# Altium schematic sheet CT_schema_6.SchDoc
size 368 x 336 mm
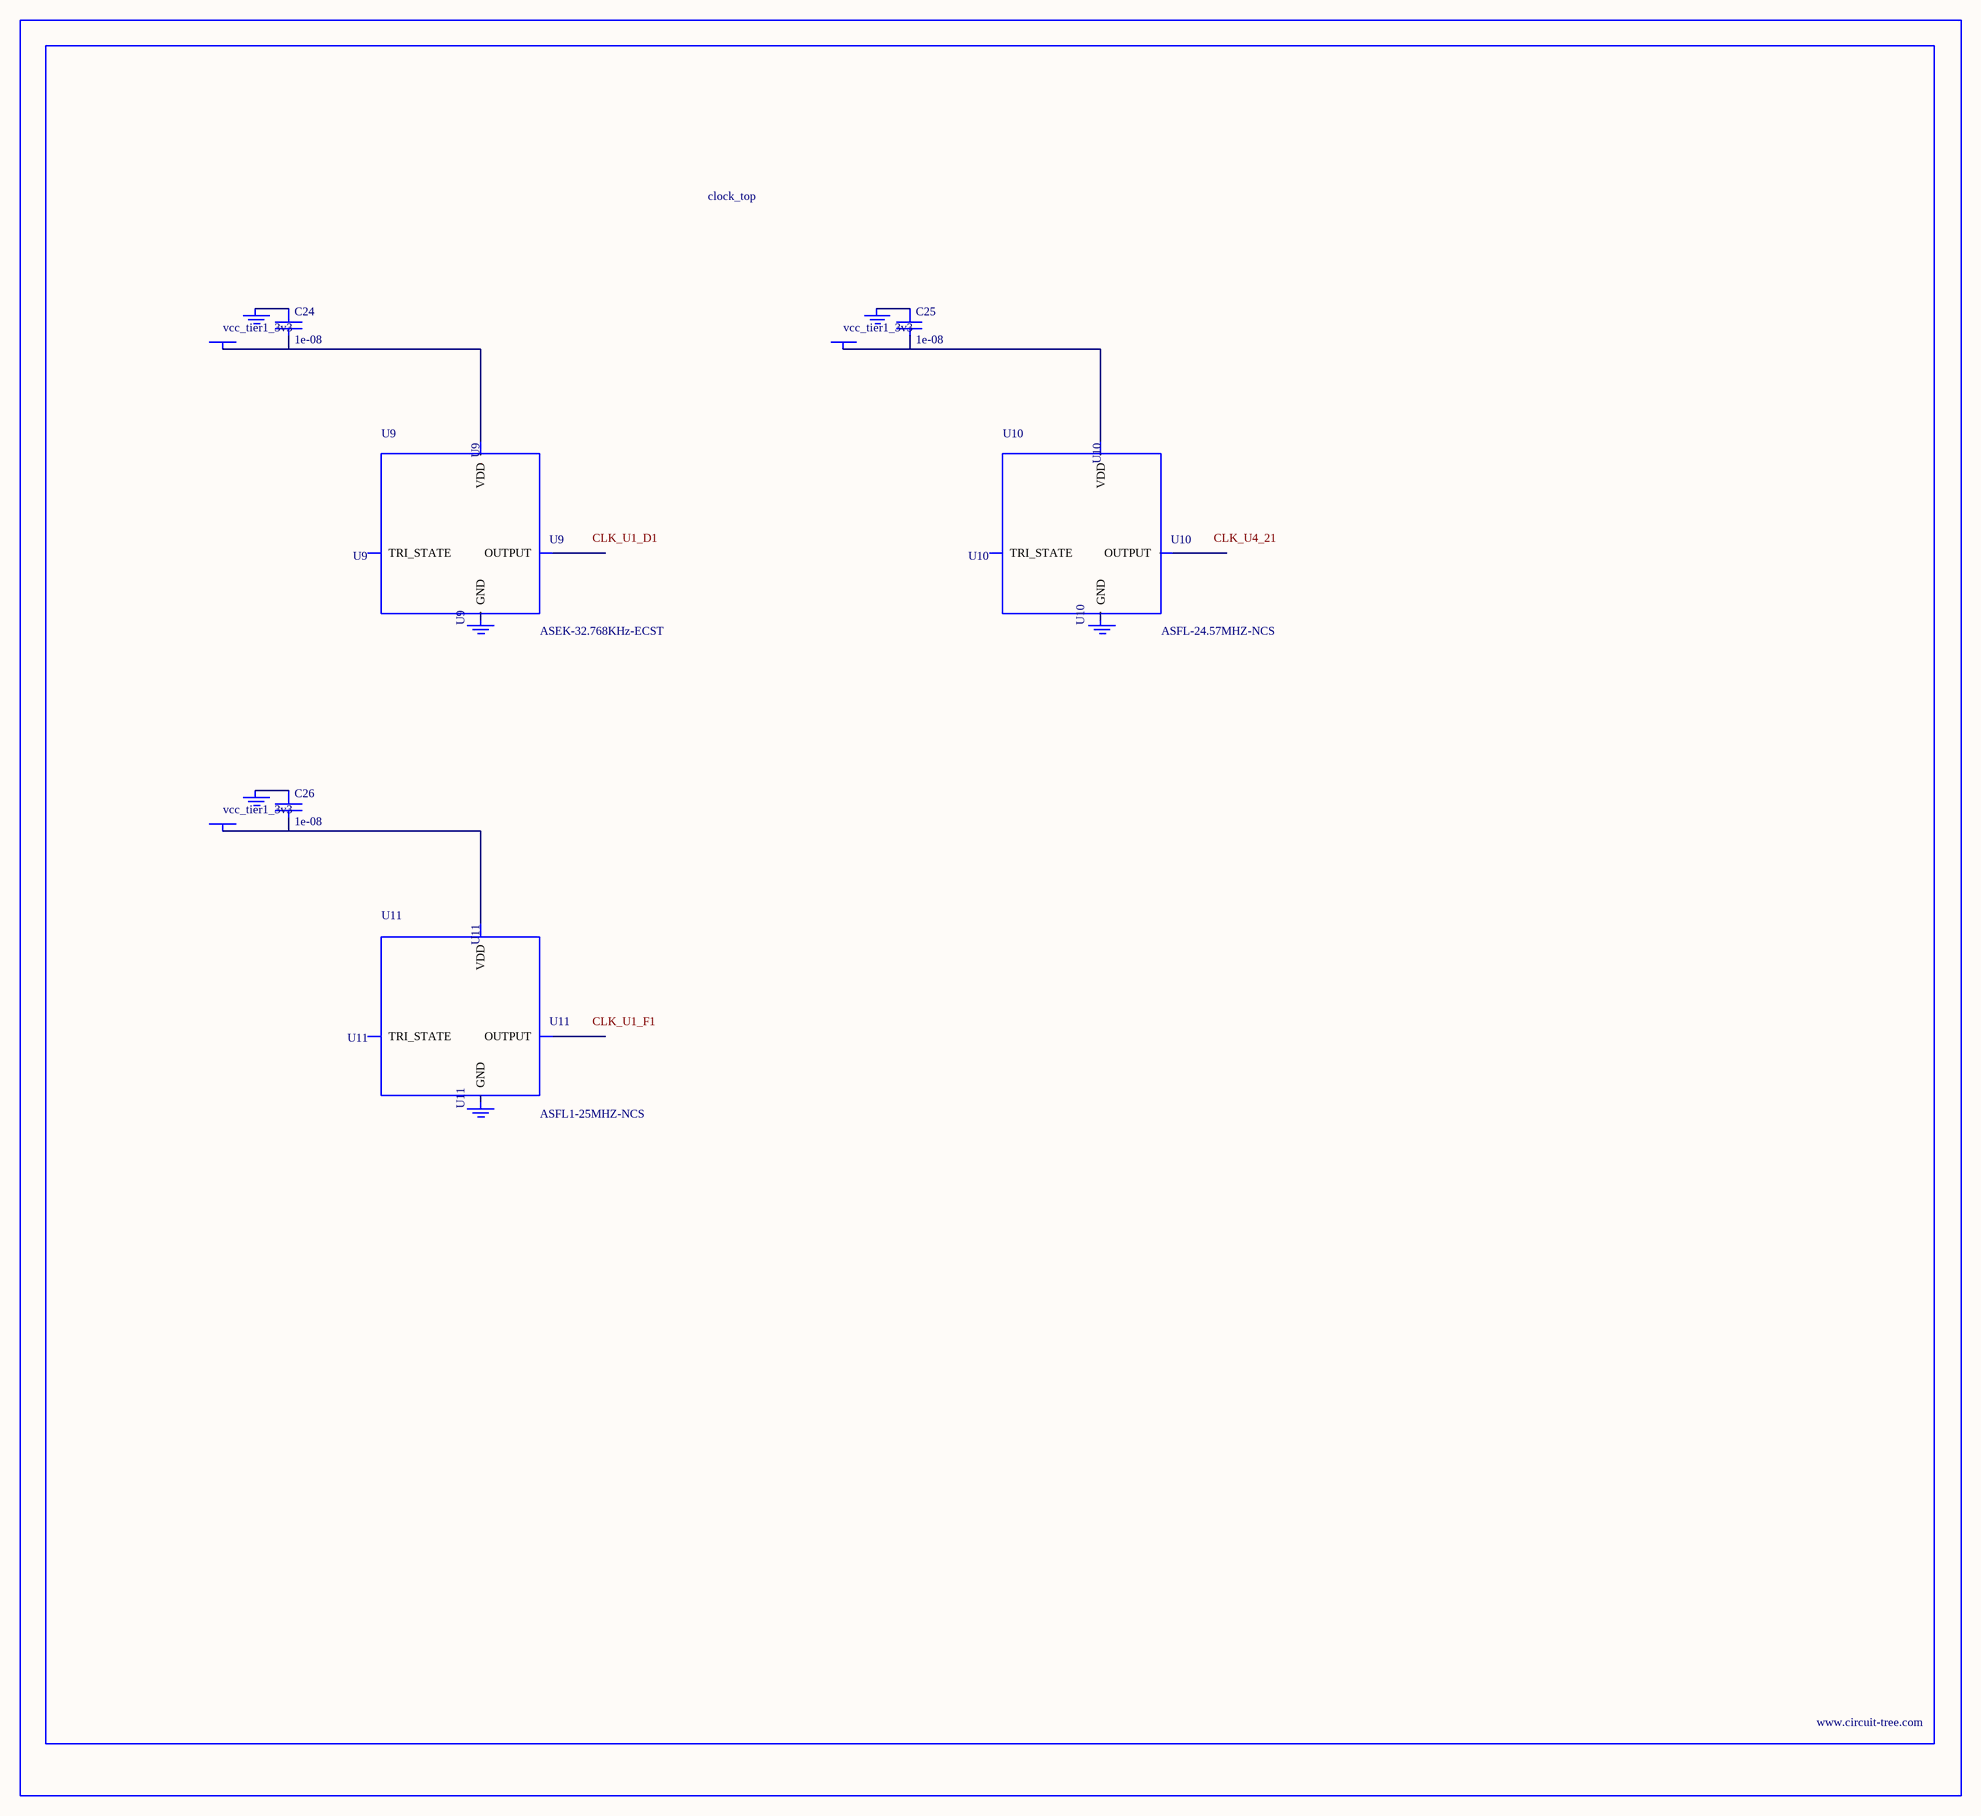
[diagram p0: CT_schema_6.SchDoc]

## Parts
BORDER5  (no value)
C24  1e-08  [C0402]
C25  1e-08  [C0402]
C26  1e-08  [C0402]
GND_INSTANCE_5_0  (no value)
GND_INSTANCE_5_1  (no value)
GND_INSTANCE_5_2  (no value)
GND_INSTANCE_5_3  (no value)
GND_INSTANCE_5_4  (no value)
GND_INSTANCE_5_5  (no value)
POWER_INSTANCE_5_0  vcc_tier1_3v3
POWER_INSTANCE_5_1  vcc_tier1_3v3
POWER_INSTANCE_5_2  vcc_tier1_3v3
U9  ASEK-32.768KHz-ECST  [ASEK]
U10  ASFL-24.57MHZ-NCS  [ASFL1]
U11  ASFL1-25MHZ-NCS  [ASFL1]

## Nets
NetC24_1: C24.1 GND_INSTANCE_5_0.0(GND)
NetC24_2: C24.2 POWER_INSTANCE_5_0.0(PWR) U9.4(VDD)
NetC25_1: C25.1 GND_INSTANCE_5_2.0(GND)
NetC25_2: C25.2 POWER_INSTANCE_5_1.0(PWR) U10.4(VDD)
NetC26_1: C26.1 GND_INSTANCE_5_4.0(GND)
NetC26_2: C26.2 POWER_INSTANCE_5_2.0(PWR) U11.4(VDD)

Not connected (* = marked no-connect by the designer): GND_INSTANCE_5_1 0(GND); GND_INSTANCE_5_3 0(GND); GND_INSTANCE_5_5 0(GND); U9 1(TRI_STATE) 2(GND) 3(OUTPUT); U10 1(TRI_STATE) 2(GND) 3(OUTPUT); U11 1(TRI_STATE) 2(GND) 3(OUTPUT)

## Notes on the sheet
- Labels drawn without touching a wire or pin: CLK_U1_D1, CLK_U1_F1, CLK_U4_21

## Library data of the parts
BORDER5 = BORDER_PAGE5
C24-C26 = C0402C103K3RAC
GND_INSTANCE_5_0-GND_INSTANCE_5_5 = GND
POWER_INSTANCE_5_0-POWER_INSTANCE_5_2 = PWR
